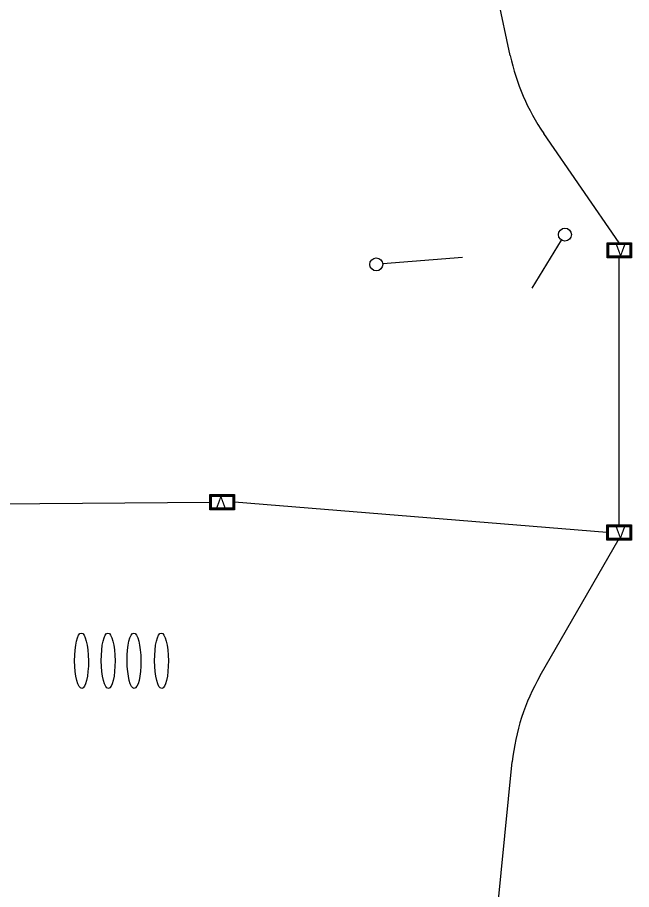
# Model space of a CAD drawing. Extents: x 584850 to 602551, y 145475 to 158627.
# Drawn here: x 594348.1 to 594631.9, y 154200.4 to 154603.4 of the extents above; entities that cross this region are included whole.
import ezdxf

# ---------------------------------------------------------------- set-up
doc = ezdxf.new("R2010")
doc.units = 0
for name, color, linetype in [('B_MISC', 7, 'Continuous'), ('Default', 7, 'Continuous'), ('E_RDWY', 7, 'Continuous')]:
    doc.layers.add(name, color=color, linetype=linetype)

msp = doc.modelspace()

# ---------------------------------------------------------------- linework, layer by layer
at = {"layer": 'B_MISC'}
for p, q in [((594575.85, 154585.84), (594527.93, 154810.82)), ((594626.26, 154499.35), (594591.38, 154549.83)), ((594626.17, 154368.89), (594626.26, 154492.3)), ((594274.39, 154378.27), (594437.1, 154379.42)), ((594620.52, 154365.36), (594448.4, 154379.42)), ((594589.67, 154299.25), (594626.17, 154362.59)), ((594469.73, 153198.28), (594576.82, 154259.36))]:
    msp.add_line(p, q, dxfattribs=at)
for centre, start, end in [((594673.66, 154606.67), 192.0252, 214.6393), ((594676.31, 154249.32), 150.0479, 174.2374)]:
    msp.add_arc(centre, 100, start, end, dxfattribs=at)
at = {"layer": 'Default'}
for p, q in [((594586.04, 154478.31), (594599.57, 154500.52)), ((594553.82, 154492.56), (594516.94, 154489.57))]:
    msp.add_line(p, q, dxfattribs=at)
for centre in [(594601.13, 154503.08), (594513.95, 154489.32)]:
    msp.add_circle(centre, 3, dxfattribs=at)
at = {"layer": 'E_RDWY'}
for points in [[(594620.61, 154499.35), (594631.91, 154499.35), (594631.91, 154492.3), (594620.61, 154492.3)], [(594620.86, 154499.1), (594631.66, 154499.1), (594631.66, 154492.55), (594620.86, 154492.55)], [(594621.11, 154498.85), (594631.41, 154498.85), (594631.41, 154492.8), (594621.11, 154492.8)], [(594621.36, 154498.6), (594631.16, 154498.6), (594631.16, 154493.05), (594621.36, 154493.05)], [(594448.4, 154375.9), (594437.1, 154375.9), (594437.1, 154382.95), (594448.4, 154382.95)], [(594448.15, 154376.15), (594437.35, 154376.15), (594437.35, 154382.7), (594448.15, 154382.7)], [(594447.9, 154376.4), (594437.6, 154376.4), (594437.6, 154382.45), (594447.9, 154382.45)], [(594447.65, 154376.65), (594437.85, 154376.65), (594437.85, 154382.2), (594447.65, 154382.2)], [(594620.52, 154368.89), (594631.82, 154368.89), (594631.82, 154361.84), (594620.52, 154361.84)], [(594620.77, 154368.64), (594631.57, 154368.64), (594631.57, 154362.09), (594620.77, 154362.09)], [(594621.02, 154368.39), (594631.32, 154368.39), (594631.32, 154362.34), (594621.02, 154362.34)], [(594621.27, 154368.14), (594631.07, 154368.14), (594631.07, 154362.59), (594621.27, 154362.59)]]:
    msp.add_lwpolyline(points, close=True, dxfattribs=at)
for centre in [(594377.76, 154306.13), (594390.06, 154306.13), (594402, 154306.13), (594414.7, 154306.13)]:
    msp.add_ellipse(centre, major_axis=(0.1, -12.82), ratio=0.249166, dxfattribs=at)

# ---------------------------------------------------------------- texts
for rotation, p in [(360, (594624.64, 154493.35)), (180, (594444.37, 154381.9)), (360, (594624.55, 154362.89))]:
    msp.add_text('V', height=4.96, rotation=rotation, dxfattribs=at).set_placement(p)

doc.saveas('drawing.dxf')
